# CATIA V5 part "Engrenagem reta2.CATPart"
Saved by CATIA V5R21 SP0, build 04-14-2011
Part number: Engrenagem reta2
Definition: Engrenagem reta2
Nomenclature: Engrenagem reta22
Source: Unknown
Bounding box of the stored display mesh (mm): x -1.796 to 1.796, y -1.8 to 1.8, z 0 to 0.5
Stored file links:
  C:\Users\beatr\OneDrive\Documents\UNB\2026_1\Pi1\Componentes eletronicos\Engrenagem reta2.CATPart
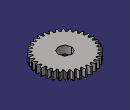
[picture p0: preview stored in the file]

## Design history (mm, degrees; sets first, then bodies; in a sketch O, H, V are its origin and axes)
Body1 "Solid1" (main body)
  Solid1: solid without history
